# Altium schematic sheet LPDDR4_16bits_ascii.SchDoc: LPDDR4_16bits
size A3; Date: Not used; ApprovedBy: Not used; CheckedBy: Not used; Author: Not used; CompanyName: STMicroelectronics; DrawnBy: Not used; Engineer: Not used; Organization: Not used; Address1: Not used; Address2: Not used; Address3: Not used; Address4: Not used; DocumentNumber: 6; Revision: Not used; SheetNumber: 6; SheetTotal: 7
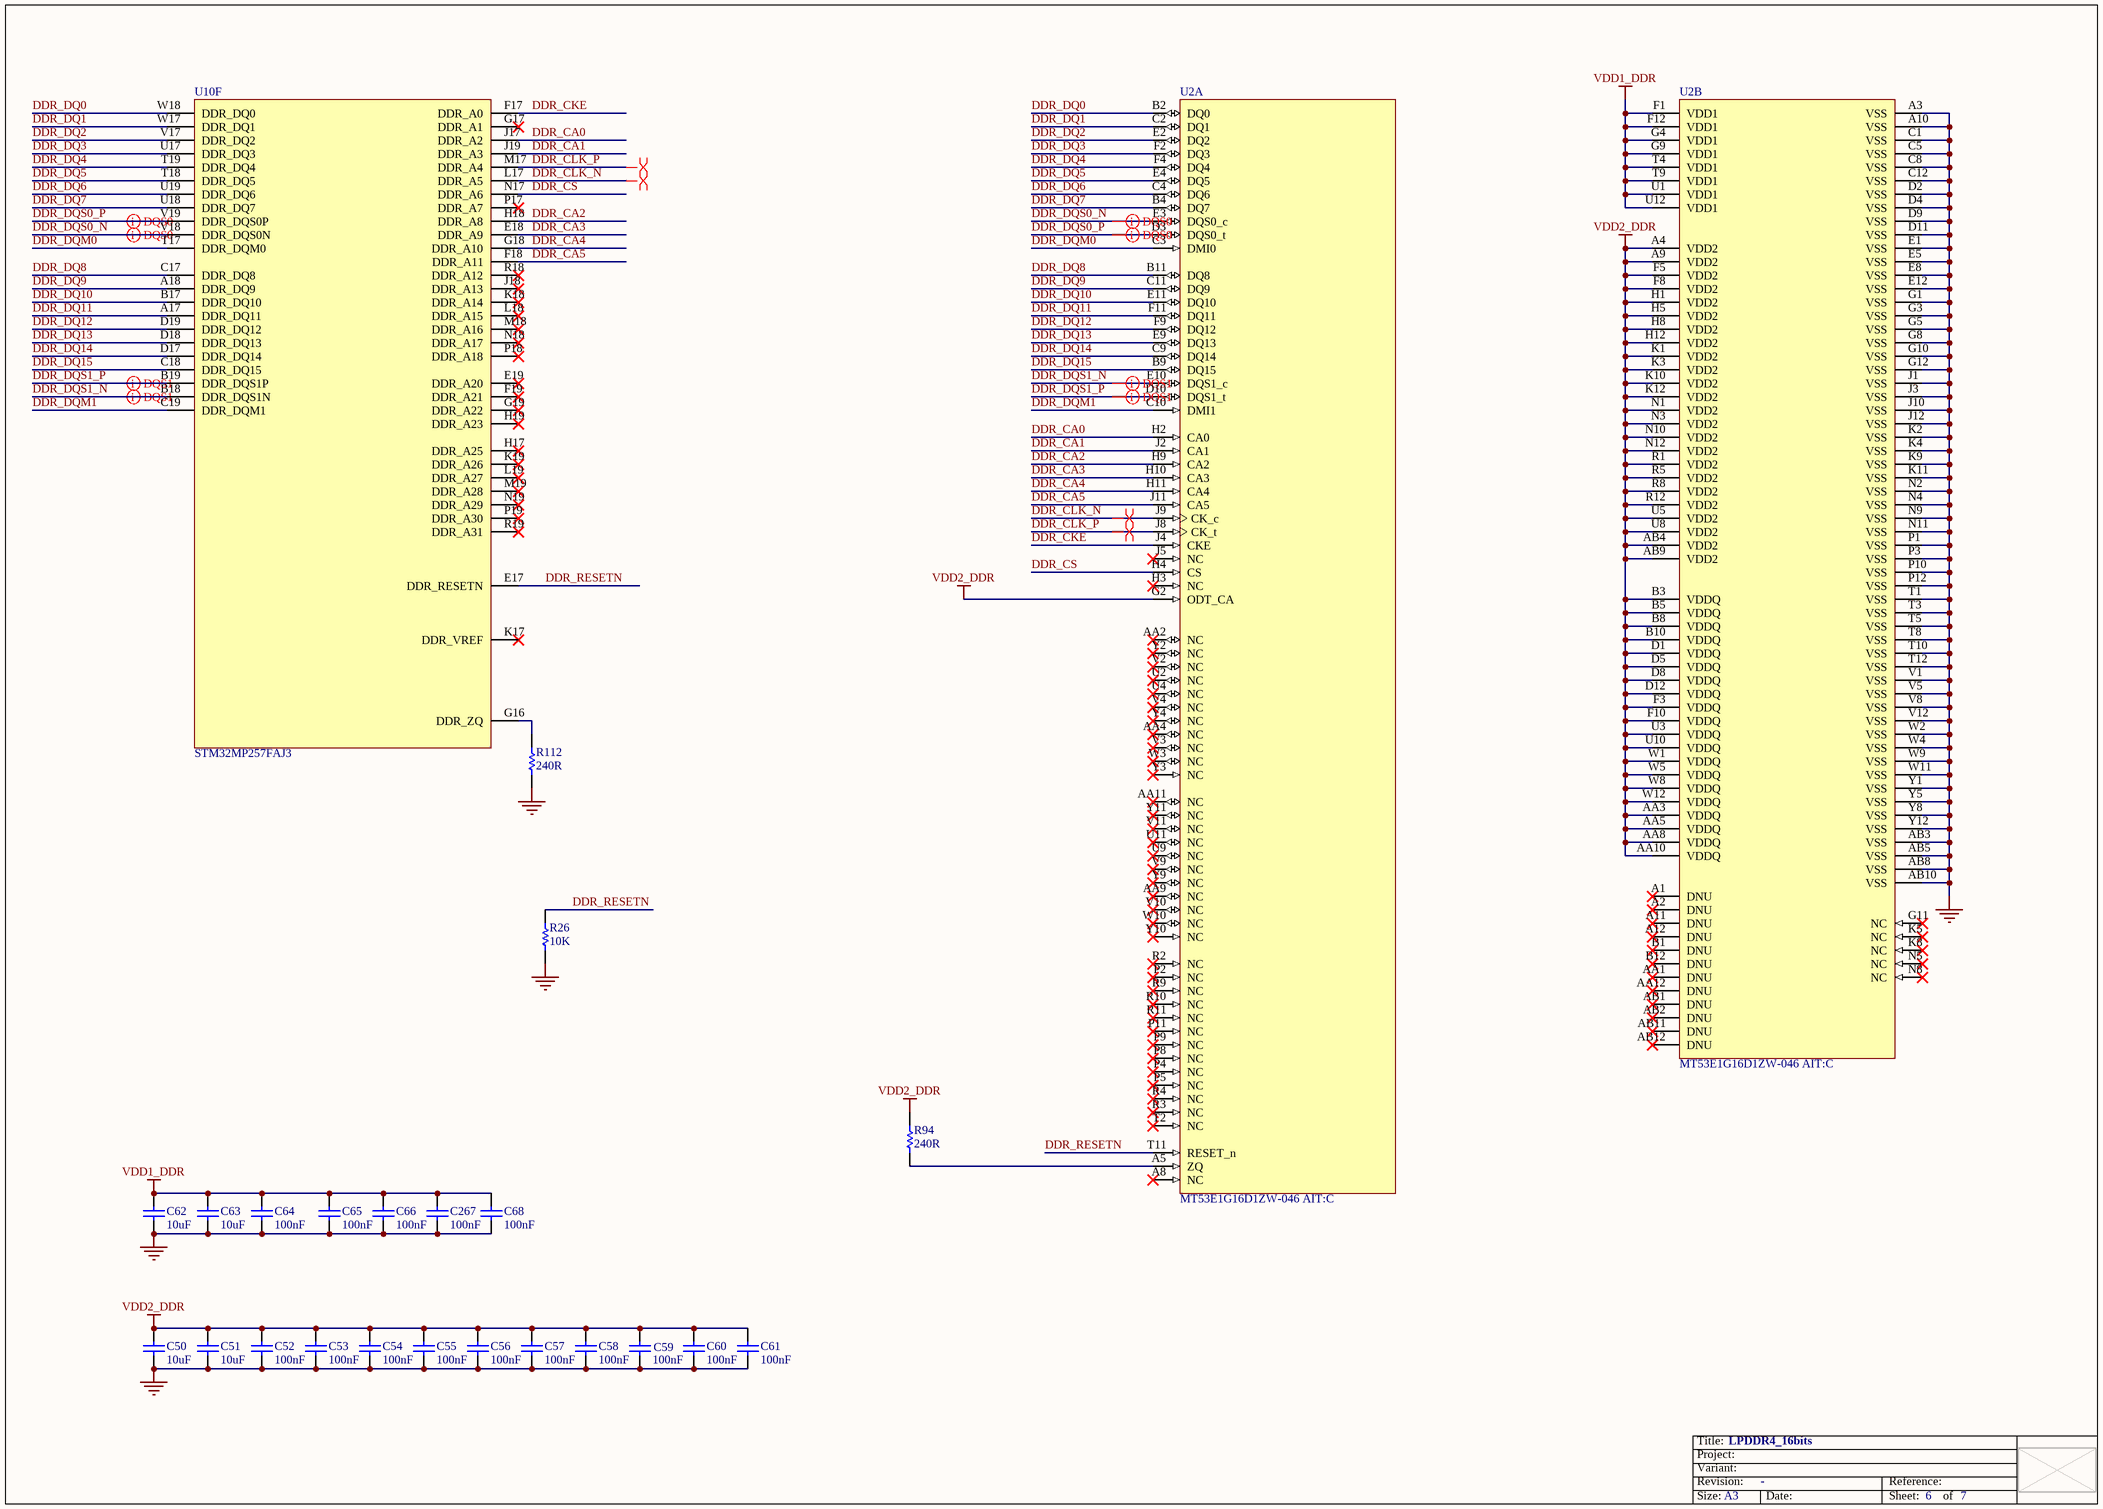
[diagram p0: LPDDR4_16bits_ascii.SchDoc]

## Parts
C50  value 10uF  [C0603]  (hidden comment: Capacitor)
C51  value 10uF  [C0603]  (hidden comment: Capacitor)
C52  value 100nF  [C0402]  (hidden comment: Capacitor)
C53  value 100nF  [C0402]  (hidden comment: Capacitor)
C54  value 100nF  [C0402]  (hidden comment: Capacitor)
C55  value 100nF  [C0402]  (hidden comment: Capacitor)
C56  value 100nF  [C0402]  (hidden comment: Capacitor)
C57  value 100nF  [C0402]  (hidden comment: Capacitor)
C58  value 100nF  [C0402]  (hidden comment: Capacitor)
C59  value 100nF  [C0402]  (hidden comment: Capacitor)
C60  value 100nF  [C0402]  (hidden comment: Capacitor)
C61  value 100nF  [C0402]  (hidden comment: Capacitor)
C62  value 10uF  [C0603]  (hidden comment: Capacitor)
C63  value 10uF  [C0603]  (hidden comment: Capacitor)
C64  value 100nF  [C0402]  (hidden comment: Capacitor)
C65  value 100nF  [C0402]  (hidden comment: Capacitor)
C66  value 100nF  [C0402]  (hidden comment: Capacitor)
C68  value 100nF  [C0402]  (hidden comment: Capacitor)
C267  value 100nF  [C0402]  (hidden comment: Capacitor)
R26  value 10K  [R0402]  (hidden comment: Resistor)
R94  value 240R  [R0201_H0P23]  (hidden comment: Resistor)
R112  value 240R  [R0201_H0P23]  (hidden comment: Resistor)
U2  MT53E1G16D1ZW-046 AIT:C  [ICC_TFBGA200_10X14P5_P080_H1P05]  (parts A,B of 2)
U10  value STM32MP257FAJ3  [ICC_TFBGA361_16X16_P080]  (hidden comment: IC_STM32MP257FAJ3)  (part F of 9)

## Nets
GND: C50.1 C51.1 C52.1 C53.2 C54.2 C55.2 C56.2 C57.2 C58.2 C59.2 C60.2 C61.2 C62.1 C63.1 C64.1 C65.1 C66.1 C68.1 C267.1 R26.1 R112.1 U2.A3(VSS) U2.A10(VSS) U2.AB3(VSS) U2.AB5(VSS) U2.AB8(VSS) U2.AB10(VSS) U2.C1(VSS) U2.C5(VSS) U2.C8(VSS) U2.C12(VSS) U2.D2(VSS) U2.D4(VSS) U2.D9(VSS) U2.D11(VSS) U2.E1(VSS) U2.E5(VSS) U2.E8(VSS) U2.E12(VSS) U2.G1(VSS) U2.G3(VSS) U2.G5(VSS) U2.G8(VSS) U2.G10(VSS) U2.G12(VSS) U2.J1(VSS) U2.J3(VSS) U2.J10(VSS) U2.J12(VSS) U2.K2(VSS) U2.K4(VSS) U2.K9(VSS) U2.K11(VSS) U2.N2(VSS) U2.N4(VSS) U2.N9(VSS) U2.N11(VSS) U2.P1(VSS) U2.P3(VSS) U2.P10(VSS) U2.P12(VSS) U2.T1(VSS) U2.T3(VSS) U2.T5(VSS) U2.T8(VSS) U2.T10(VSS) U2.T12(VSS) U2.V1(VSS) U2.V5(VSS) U2.V8(VSS) U2.V12(VSS) U2.W2(VSS) U2.W4(VSS) U2.W9(VSS) U2.W11(VSS) U2.Y1(VSS) U2.Y5(VSS) U2.Y8(VSS) U2.Y12(VSS)
VDD1_DDR: C62.2 C63.2 C64.2 C65.2 C66.2 C68.2 C267.2 U2.F1(VDD1) U2.F12(VDD1) U2.G4(VDD1) U2.G9(VDD1) U2.T4(VDD1) U2.T9(VDD1) U2.U1(VDD1) U2.U12(VDD1)
VDD2_DDR: C50.2 C51.2 C52.2 C53.1 C54.1 C55.1 C56.1 C57.1 C58.1 C59.1 C60.1 C61.1 R94.2 U2.A4(VDD2) U2.A9(VDD2) U2.AA3(VDDQ) U2.AA5(VDDQ) U2.AA8(VDDQ) U2.AA10(VDDQ) U2.AB4(VDD2) U2.AB9(VDD2) U2.B3(VDDQ) U2.B5(VDDQ) U2.B8(VDDQ) U2.B10(VDDQ) U2.D1(VDDQ) U2.D5(VDDQ) U2.D8(VDDQ) U2.D12(VDDQ) U2.F3(VDDQ) U2.F5(VDD2) U2.F8(VDD2) U2.F10(VDDQ) U2.G2(ODT_CA) U2.H1(VDD2) U2.H5(VDD2) U2.H8(VDD2) U2.H12(VDD2) U2.K1(VDD2) U2.K3(VDD2) U2.K10(VDD2) U2.K12(VDD2) U2.N1(VDD2) U2.N3(VDD2) U2.N10(VDD2) U2.N12(VDD2) U2.R1(VDD2) U2.R5(VDD2) U2.R8(VDD2) U2.R12(VDD2) U2.U3(VDDQ) U2.U5(VDD2) U2.U8(VDD2) U2.U10(VDDQ) U2.W1(VDDQ) U2.W5(VDDQ) U2.W8(VDDQ) U2.W12(VDDQ)
DDR_CA0: U2.H2(CA0) U10.J17(DDR_A2)
DDR_CA1: U2.J2(CA1) U10.J19(DDR_A3)
DDR_CA2: U2.H9(CA2) U10.H18(DDR_A8)
DDR_CA3: U2.H10(CA3) U10.E18(DDR_A9)
DDR_CA4: U2.H11(CA4) U10.G18(DDR_A10)
DDR_CA5: U2.J11(CA5) U10.F18(DDR_A11)
DDR_CKE: U2.J4(CKE) U10.F17(DDR_A0)
DDR_CLK_N: U2.J9(CK_c) U10.L17(DDR_A5)
DDR_CLK_P: U2.J8(CK_t) U10.M17(DDR_A4)
DDR_CS: U2.H4(CS) U10.N17(DDR_A6)
DDR_DQ0: U2.B2(DQ0) U10.W18(DDR_DQ0)
DDR_DQ1: U2.C2(DQ1) U10.W17(DDR_DQ1)
DDR_DQ2: U2.E2(DQ2) U10.V17(DDR_DQ2)
DDR_DQ3: U2.F2(DQ3) U10.U17(DDR_DQ3)
DDR_DQ4: U2.F4(DQ4) U10.T19(DDR_DQ4)
DDR_DQ5: U2.E4(DQ5) U10.T18(DDR_DQ5)
DDR_DQ6: U2.C4(DQ6) U10.U19(DDR_DQ6)
DDR_DQ7: U2.B4(DQ7) U10.U18(DDR_DQ7)
DDR_DQ8: U2.B11(DQ8) U10.C17(DDR_DQ8)
DDR_DQ9: U2.C11(DQ9) U10.A18(DDR_DQ9)
DDR_DQ10: U2.E11(DQ10) U10.B17(DDR_DQ10)
DDR_DQ11: U2.F11(DQ11) U10.A17(DDR_DQ11)
DDR_DQ12: U2.F9(DQ12) U10.D19(DDR_DQ12)
DDR_DQ13: U2.E9(DQ13) U10.D18(DDR_DQ13)
DDR_DQ14: U2.C9(DQ14) U10.D17(DDR_DQ14)
DDR_DQ15: U2.B9(DQ15) U10.C18(DDR_DQ15)
DDR_DQM0: U2.C3(DMI0) U10.T17(DDR_DQM0)
DDR_DQM1: U2.C10(DMI1) U10.C19(DDR_DQM1)
DDR_DQS0_N: U2.E3(DQS0_c) U10.V18(DDR_DQS0N)
DDR_DQS0_P: U2.D3(DQS0_t) U10.V19(DDR_DQS0P)
DDR_DQS1_N: U2.E10(DQS1_c) U10.B18(DDR_DQS1N)
DDR_DQS1_P: U2.D10(DQS1_t) U10.B19(DDR_DQS1P)
DDR_RESETN: R26.2 U2.T11(RESET_n) U10.E17(DDR_RESETN)
NetR94_1: R94.1 U2.A5(ZQ)
NetR112_2: R112.2 U10.G16(DDR_ZQ)

Not connected (* = marked no-connect by the designer): U2 A1(DNU)* A2(DNU)* A8(NC)* A11(DNU)* A12(DNU)* AA1(DNU)* AA2(NC)* AA4(NC)* AA9(NC)* AA11(NC)* AA12(DNU)* AB1(DNU)* AB2(DNU)* AB11(DNU)* AB12(DNU)* B1(DNU)* B12(DNU)* G11(NC)* H3(NC)* J5(NC)* K5(NC)* K8(NC)* N5(NC)* N8(NC)* P2(NC)* P4(NC)* P5(NC)* P8(NC)* P9(NC)* P11(NC)* R2(NC)* R3(NC)* R4(NC)* R9(NC)* R10(NC)* R11(NC)* T2(NC)* U2(NC)* U4(NC)* U9(NC)* U11(NC)* V2(NC)* V3(NC)* V4(NC)* V9(NC)* V10(NC)* V11(NC)* W3(NC)* W10(NC)* Y2(NC)* Y3(NC)* Y4(NC)* Y9(NC)* Y10(NC)* Y11(NC)*; U10 E19(DDR_A20)* F19(DDR_A21)* G17(DDR_A1)* G19(DDR_A22)* H17(DDR_A25)* H19(DDR_A23)* J18(DDR_A13)* K17(DDR_VREF)* K18(DDR_A14)* K19(DDR_A26)* L18(DDR_A15)* L19(DDR_A27)* M18(DDR_A16)* M19(DDR_A28)* N18(DDR_A17)* N19(DDR_A29)* P17(DDR_A7)* P18(DDR_A18)* P19(DDR_A30)* R18(DDR_A12)* R19(DDR_A31)*

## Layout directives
differential pair: DDR_CLK_N, DDR_CLK_P, DDR_DQS0_N, DDR_DQS0_P, DDR_DQS1_N, DDR_DQS1_P

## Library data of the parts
C50 C51 C62 C63 = MCD-01341: Capacitor, MLCC, 10uF, 6V3, X5R, +/-20%, 0603, T=0.8mm; Part_Preference: Recommended; Manufacturer: MURATA; Manufacturer_Part_Number: GRM188R60J106ME47D; Component_Country_Of_Origin: Japan°°; ShowFields: YES; ID: 3441
C52-C61 C64-C66 C68 C267 = MCD-00006: Capacitor, MLCC, 100nF, 16V, X7R, +/-10%, 0402, T=0.5mm; Part_Preference: Recommended; Manufacturer: YAGEO; Manufacturer_Part_Number: CC0402KRX7R7BB104; Partial_Alternate_Internal_Part_Number: MCD-03299; Order_Code_RS: 9402047; Component_Country_Of_Origin: China; ShowFields: YES; ID: 2474
R26 = MCD-00053: Resistor, 10K, 0402, +/-1%, 1/16W; BMS_Part_Number: 9131590; Part_Preference: Recommended; Manufacturer: YAGEO; Manufacturer_Part_Number: RC0402FR-0710KL; Order_Code_RS: 9239359; Component_Country_Of_Origin: China; ShowFields: YES; ID: 2539
R94 = MCD-02253: Resistor, 240R, 0201, +/-1%, 1/20W; Part_Preference: Recommended; Manufacturer: YAGEO; Manufacturer_Part_Number: RC0201FR-07240RL; Component_Country_Of_Origin: China; ShowFields: YES; ID: 4353
R112 = MCD-02253: Resistor,240R,0201,1%,1/20W; Part_Preference: Recommended; Manufacturer: YAGEO; Manufacturer_Part_Number: RC0201FR-07240RL
U2 = MCD-04012: Memory, SDRAM, 1V1, 16Gbit, 4266MHz; Part_Type: IC; Part_Preference: Recommended; Manufacturer: MICRON; Component_Country_Of_Origin: Taiwan°; ShowFields: YES; ID: 6128
U10 = MCD-04441: MPU, Dual Core ARM cortex-A35 64-bit + M33 32-bit,  808KB SRAM, With Crypto; Part_Type: IC; Part_Preference: Recommended; Manufacturer: STMICROELECTRONICS; ShowFields: YES; ID: 6557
